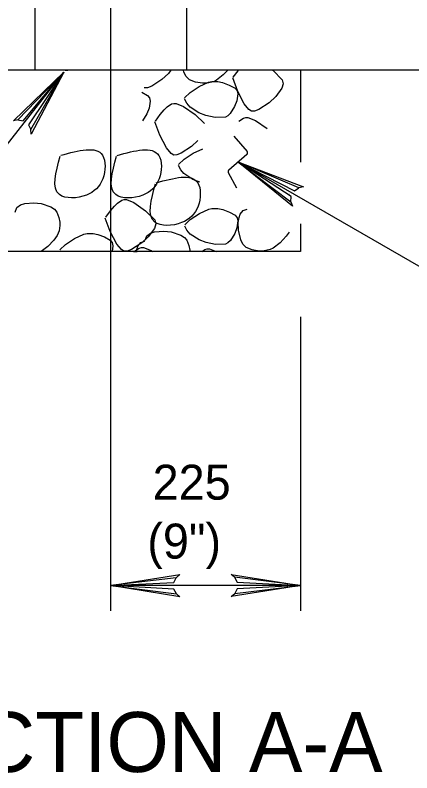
# Model space of a CAD drawing. Extents: x 638455 to 640199, y 298558 to 299152.
# Drawn here: x 638664.2 to 638702.3, y 298629.5 to 298702.3 of the extents above; entities that cross this region are included whole.
import ezdxf

# ---------------------------------------------------------------- set-up
doc = ezdxf.new("R2010")
doc.units = 0
for name, color, linetype in [('1', 7, 'Continuous'), ('2', 7, 'Continuous'), ('3', 7, 'Continuous')]:
    doc.layers.add(name, color=color, linetype=linetype)

msp = doc.modelspace()

# ---------------------------------------------------------------- linework, layer by layer
at = {"layer": '1'}
for p, q in [((638685.258, 298690.722), (638686.526, 298689.235)), ((638686.504, 298688.953), (638684.755, 298687.453)), ((638684.709, 298687.206), (638685.499, 298685.757))]:
    msp.add_line(p, q, dxfattribs=at)
for centre, start, end in [((638686.374, 298689.105), 310.61752, 40.44601), ((638684.885, 298687.301), 130.61752, 208.59666)]:
    msp.add_arc(centre, 0.2, start, end, dxfattribs=at)
at = {"layer": '2'}
for p, q in [((638673.404, 298728.014), (638673.404, 298653.302)), ((638666.121, 298713.622), (638666.121, 298697.041)), ((638680.687, 298713.622), (638680.687, 298697.041)), ((638736.215, 298697.041), (638610.593, 298697.041)), ((638669.025, 298697.041), (638669.297, 298697.041)), ((638691.649, 298697.041), (638691.649, 298688.213)), ((638721.984, 298667.253), (638685.64, 298688.239)), ((638691.649, 298682.297), (638691.649, 298679.617)), ((638691.649, 298679.617), (638569.754, 298679.617)), ((638691.649, 298673.369), (638691.649, 298645.097)), ((638673.404, 298653.302), (638673.404, 298645.097)), ((638691.649, 298647.537), (638673.404, 298647.537))]:
    msp.add_line(p, q, dxfattribs=at)
for points in [[(638679.193, 298697.041), (638678.966, 298696.733)], [(638680.45, 298696.861), (638680.407, 298697.041)], [(638684.667, 298697.041), (638684.234, 298696.585)], [(638685.193, 298696.382), (638685.648, 298697)], [(638685.648, 298697), (638685.683, 298697.041)], [(638688.959, 298697.041), (638689.014, 298697.004)], [(638689.014, 298697.004), (638689.894, 298696.127)], [(638689.061, 298697.041), (638689.064, 298697.041)], [(638689.064, 298697.041), (638689.064, 298697.041)], [(638631.938, 298649.672), (638668.925, 298696.862)], [(638664.494, 298692.271), (638665.002, 298692.186), (638668.925, 298696.862), (638664.494, 298692.271), (638664.079, 298692.179), (638668.925, 298696.862), (638665.514, 298691.807), (638665.745, 298691.357), (638668.925, 298696.862), (638665.783, 298690.902), (638665.745, 298691.357)], [(638678.966, 298696.733), (638678.339, 298696.156)], [(638680.665, 298696.443), (638680.45, 298696.861)], [(638680.982, 298696.129), (638680.665, 298696.443)], [(638684.234, 298696.585), (638683.572, 298696.074)], [(638685.617, 298695.009), (638685.137, 298696.298)], [(638677.36, 298695.511), (638676.945, 298695.354)], [(638678.339, 298696.156), (638677.36, 298695.511)], [(638681.554, 298695.897), (638680.982, 298696.129)], [(638681.043, 298694.895), (638681.92, 298695.476)], [(638682.233, 298695.787), (638681.554, 298695.897)], [(638681.92, 298695.476), (638682.826, 298695.886)], [(638682.698, 298695.793), (638682.233, 298695.787)], [(638683.282, 298695.926), (638682.698, 298695.793)], [(638682.826, 298695.886), (638683.122, 298695.958)], [(638683.122, 298695.958), (638683.703, 298695.952)], [(638683.572, 298696.074), (638683.282, 298695.926)], [(638683.703, 298695.952), (638684.156, 298695.859)], [(638684.156, 298695.859), (638684.809, 298695.621)], [(638684.809, 298695.621), (638685.361, 298695.322)], [(638689.999, 298695.732), (638689.865, 298695.308)], [(638689.894, 298696.127), (638689.999, 298695.732)], [(638676.394, 298694.921), (638676.942, 298694.622)], [(638676.945, 298695.354), (638676.637, 298695.345)], [(638680.517, 298694.393), (638681.043, 298694.895)], [(638685.361, 298695.322), (638685.556, 298695.075)], [(638685.617, 298694.764), (638685.518, 298694.094)], [(638685.556, 298695.075), (638685.617, 298694.764)], [(638686.247, 298693.8), (638685.617, 298695.009)], [(638689.865, 298695.308), (638689.267, 298694.503)], [(638676.942, 298694.622), (638677.14, 298694.376)], [(638677.198, 298694.065), (638677.102, 298693.394)], [(638677.14, 298694.376), (638677.198, 298694.065)], [(638680.72, 298693.87), (638680.517, 298694.28)], [(638685.518, 298694.094), (638685.318, 298693.565)], [(638689.267, 298694.503), (638688.643, 298693.925)], [(638677.102, 298693.394), (638676.902, 298692.865)], [(638678.542, 298693.228), (638678.83, 298693.513)], [(638678.83, 298693.513), (638679.263, 298693.8)], [(638679.263, 298693.8), (638679.477, 298693.862)], [(638679.477, 298693.862), (638679.692, 298693.853)], [(638679.692, 298693.853), (638680.404, 298693.565)], [(638680.404, 298693.565), (638681.542, 298692.787)], [(638681.034, 298693.51), (638680.72, 298693.87)], [(638681.894, 298692.949), (638681.034, 298693.51)], [(638685.318, 298693.565), (638684.897, 298692.886)], [(638686.694, 298693.263), (638686.247, 298693.8)], [(638687.661, 298693.281), (638687.246, 298693.124)], [(638688.643, 298693.925), (638687.661, 298693.281)], [(638676.902, 298692.865), (638676.481, 298692.186)], [(638677.72, 298692.163), (638678.176, 298692.781)], [(638678.176, 298692.781), (638678.542, 298693.228)], [(638681.542, 298692.787), (638682.422, 298691.91)], [(638682.562, 298692.694), (638681.894, 298692.949)], [(638683.453, 298692.505), (638682.562, 298692.694)], [(638684.661, 298692.656), (638684.432, 298692.534)], [(638684.897, 298692.886), (638684.661, 298692.656)], [(638686.941, 298693.115), (638686.694, 298693.263)], [(638687.246, 298693.124), (638686.941, 298693.115)], [(638678.142, 298690.792), (638677.665, 298692.078)], [(638684.432, 298692.534), (638683.453, 298692.505)], [(638685.739, 298692.157), (638686.174, 298692.444)], [(638686.174, 298692.444), (638686.389, 298692.505)], [(638686.389, 298692.505), (638686.601, 298692.497)], [(638686.601, 298692.497), (638687.312, 298692.212)], [(638687.312, 298692.212), (638688.451, 298691.431)], [(638678.775, 298689.581), (638678.142, 298690.792)], [(638681.168, 298689.709), (638680.189, 298689.064)], [(638681.795, 298690.284), (638681.168, 298689.709)], [(638679.219, 298689.044), (638678.775, 298689.581)], [(638679.466, 298688.898), (638679.219, 298689.044)], [(638679.774, 298688.904), (638679.466, 298688.898)], [(638680.189, 298689.064), (638679.774, 298688.904)], [(638680.465, 298688.495), (638681.342, 298689.076)], [(638681.342, 298689.076), (638682.251, 298689.485)], [(638679.942, 298687.992), (638680.465, 298688.495)], [(638690.725, 298684.385), (638690.749, 298684.899), (638685.64, 298688.239), (638690.725, 298684.385), (638690.868, 298683.982), (638685.64, 298688.239), (638691.065, 298685.454), (638691.483, 298685.736), (638685.64, 298688.239), (638691.933, 298685.826), (638691.483, 298685.736)], [(638680.145, 298687.47), (638679.942, 298687.882)], [(638680.456, 298687.113), (638680.145, 298687.47)], [(638681.316, 298686.549), (638680.456, 298687.113)], [(638681.984, 298686.294), (638681.316, 298686.549)], [(638674.057, 298684.272), (638674.49, 298684.563)], [(638674.49, 298684.563), (638674.705, 298684.624)], [(638674.705, 298684.624), (638674.92, 298684.612)], [(638674.92, 298684.612), (638675.631, 298684.328)], [(638690.562, 298685.109), (638690.481, 298685.065)], [(638664.248, 298683.419), (638664.401, 298683.846)], [(638664.401, 298683.846), (638664.738, 298684.098)], [(638664.738, 298684.098), (638665.15, 298684.237)], [(638665.15, 298684.237), (638666.025, 298684.307)], [(638666.025, 298684.307), (638666.724, 298684.226)], [(638666.724, 298684.226), (638667.663, 298683.918)], [(638667.663, 298683.918), (638668.014, 298683.692)], [(638673.404, 298683.544), (638673.77, 298683.988)], [(638673.77, 298683.988), (638674.057, 298684.272)], [(638675.631, 298684.328), (638676.77, 298683.546)], [(638668.014, 298683.692), (638668.246, 298683.419)], [(638668.246, 298683.419), (638668.444, 298682.91)], [(638672.948, 298682.925), (638673.404, 298683.544)], [(638676.77, 298683.546), (638677.649, 298682.669)], [(638681.06, 298682.693), (638681.94, 298683.273)], [(638681.94, 298683.273), (638682.846, 298683.683)], [(638682.846, 298683.683), (638683.142, 298683.756)], [(638683.142, 298683.756), (638683.723, 298683.75)], [(638683.723, 298683.75), (638684.176, 298683.657)], [(638684.176, 298683.657), (638684.83, 298683.419)], [(638684.83, 298683.419), (638685.381, 298683.12)], [(638685.381, 298683.12), (638685.576, 298682.873)], [(638685.753, 298682.902), (638685.866, 298683.221)], [(638685.866, 298683.221), (638686.133, 298683.569)], [(638686.133, 298683.569), (638686.52, 298683.706)], [(638668.444, 298682.91), (638668.522, 298682.463)], [(638668.522, 298682.463), (638668.534, 298682.115)], [(638673.369, 298681.554), (638672.893, 298682.838)], [(638677.649, 298682.669), (638677.751, 298682.275)], [(638680.538, 298682.19), (638681.06, 298682.693)], [(638685.634, 298682.562), (638685.538, 298681.891)], [(638685.576, 298682.873), (638685.634, 298682.562)], [(638685.672, 298682.402), (638685.753, 298682.902)], [(638685.686, 298681.673), (638685.672, 298682.402)], [(638668.534, 298682.115), (638668.464, 298681.609)], [(638677.618, 298681.85), (638677.022, 298681.046)], [(638677.751, 298682.275), (638677.618, 298681.85)], [(638680.741, 298681.668), (638680.538, 298682.077)], [(638681.055, 298681.308), (638680.741, 298681.668)], [(638685.538, 298681.891), (638685.338, 298681.363)], [(638685.904, 298680.75), (638685.686, 298681.673)], [(638668.275, 298681.168), (638667.944, 298680.718)], [(638668.464, 298681.609), (638668.275, 298681.168)], [(638669.936, 298680.886), (638670.842, 298681.296)], [(638670.842, 298681.296), (638671.142, 298681.368)], [(638671.142, 298681.368), (638671.719, 298681.363)], [(638671.719, 298681.363), (638672.176, 298681.27)], [(638672.176, 298681.27), (638672.829, 298681.028)], [(638672.829, 298681.028), (638673.378, 298680.732)], [(638674.002, 298680.343), (638673.369, 298681.554)], [(638677.022, 298681.046), (638676.395, 298680.468)], [(638676.739, 298680.703), (638676.893, 298681.127)], [(638676.893, 298681.127), (638677.23, 298681.383)], [(638677.23, 298681.383), (638677.639, 298681.522)], [(638677.639, 298681.522), (638678.516, 298681.589)], [(638678.516, 298681.589), (638679.213, 298681.511)], [(638679.213, 298681.511), (638680.151, 298681.203)], [(638680.151, 298681.203), (638680.503, 298680.973)], [(638680.503, 298680.973), (638680.735, 298680.703)], [(638681.914, 298680.747), (638681.055, 298681.308)], [(638685.338, 298681.363), (638684.917, 298680.683)], [(638690.271, 298681.087), (638689.688, 298680.474)], [(638690.562, 298681.484), (638690.271, 298681.087)], [(638667.944, 298680.718), (638667.361, 298680.102)], [(638668.537, 298679.803), (638669.06, 298680.302)], [(638669.06, 298680.302), (638669.936, 298680.886)], [(638673.378, 298680.732), (638673.572, 298680.486)], [(638673.633, 298680.172), (638673.552, 298679.617)], [(638673.572, 298680.486), (638673.633, 298680.172)], [(638674.446, 298679.806), (638674.002, 298680.343)], [(638676.395, 298680.468), (638675.416, 298679.823)], [(638676.031, 298680.134), (638676.298, 298680.483)], [(638676.298, 298680.483), (638676.681, 298680.619)], [(638680.735, 298680.703), (638680.932, 298680.195)], [(638680.932, 298680.195), (638681.014, 298679.748)], [(638682.582, 298680.491), (638681.914, 298680.747)], [(638683.473, 298680.302), (638682.582, 298680.491)], [(638684.452, 298680.332), (638683.473, 298680.302)], [(638684.681, 298680.453), (638684.452, 298680.332)], [(638684.917, 298680.683), (638684.681, 298680.453)], [(638686.116, 298680.329), (638685.904, 298680.75)], [(638686.435, 298680.018), (638686.116, 298680.329)], [(638689.688, 298680.474), (638689.023, 298679.96)], [(638667.361, 298680.102), (638666.731, 298679.617)], [(638668.571, 298679.617), (638668.537, 298679.69)], [(638674.693, 298679.658), (638674.446, 298679.806)], [(638675.001, 298679.667), (638674.693, 298679.658)], [(638675.416, 298679.823), (638675.001, 298679.667)], [(638675.599, 298679.617), (638675.614, 298679.62)], [(638675.614, 298679.62), (638675.953, 298679.617)], [(638675.67, 298679.617), (638675.716, 298679.664)], [(638675.716, 298679.664), (638676.152, 298679.951)], [(638675.885, 298679.617), (638675.917, 298679.815)], [(638675.917, 298679.815), (638676.031, 298680.134)], [(638676.152, 298679.951), (638676.367, 298680.012)], [(638676.367, 298680.012), (638676.579, 298680.004)], [(638676.579, 298680.004), (638677.293, 298679.719)], [(638677.293, 298679.719), (638677.439, 298679.617)], [(638681.014, 298679.748), (638681.017, 298679.617)], [(638682.155, 298679.617), (638682.472, 298679.829)], [(638682.472, 298679.829), (638682.689, 298679.89)], [(638682.689, 298679.89), (638682.901, 298679.879)], [(638682.901, 298679.879), (638683.558, 298679.617)], [(638687.008, 298679.786), (638686.435, 298680.018)], [(638687.687, 298679.672), (638687.008, 298679.786)], [(638688.152, 298679.681), (638687.687, 298679.672)], [(638688.736, 298679.815), (638688.152, 298679.681)], [(638689.023, 298679.96), (638688.736, 298679.815)], [(638679.734, 298646.741), (638679.496, 298647.2), (638673.404, 298647.537), (638679.734, 298646.741), (638680.057, 298646.462), (638673.404, 298647.537), (638679.494, 298647.836), (638679.714, 298648.289), (638673.404, 298647.537), (638680.057, 298648.594), (638679.714, 298648.289)], [(638685.318, 298648.33), (638685.556, 298647.871), (638691.649, 298647.537), (638685.318, 298648.33), (638684.996, 298648.608), (638691.649, 298647.537), (638685.559, 298647.235), (638685.338, 298646.782), (638691.649, 298647.537), (638684.996, 298646.48), (638685.338, 298646.782)]]:
    msp.add_lwpolyline(points, dxfattribs=at)
for points in [[(638668.633, 298688.872), (638672.628, 298688.872), (638672.657, 298686.622), (638671.08, 298685.045), (638668.49, 298685.1), (638668.574, 298688.788)], [(638674.043, 298688.864), (638678.039, 298688.864), (638678.068, 298686.61), (638676.491, 298685.033), (638673.9, 298685.092), (638673.984, 298688.78)], [(638677.782, 298686.23), (638681.781, 298686.23), (638681.806, 298683.979), (638680.23, 298682.402), (638677.642, 298682.457), (638677.726, 298686.145)]]:
    msp.add_spline(points, degree=3, dxfattribs=at)

# ---------------------------------------------------------------- texts
at = {"layer": '1'}
msp.add_text('(9")', height=3.36, dxfattribs=at).set_placement((638676.932, 298650.129))
at = {"layer": '3'}
for s, height, p in [('225', 3.36, (638677.446, 298655.789)), ('SECTION A-A', 5.76, (638650.322, 298629.63))]:
    msp.add_text(s, height=height, dxfattribs=at).set_placement(p)

doc.saveas('drawing.dxf')
